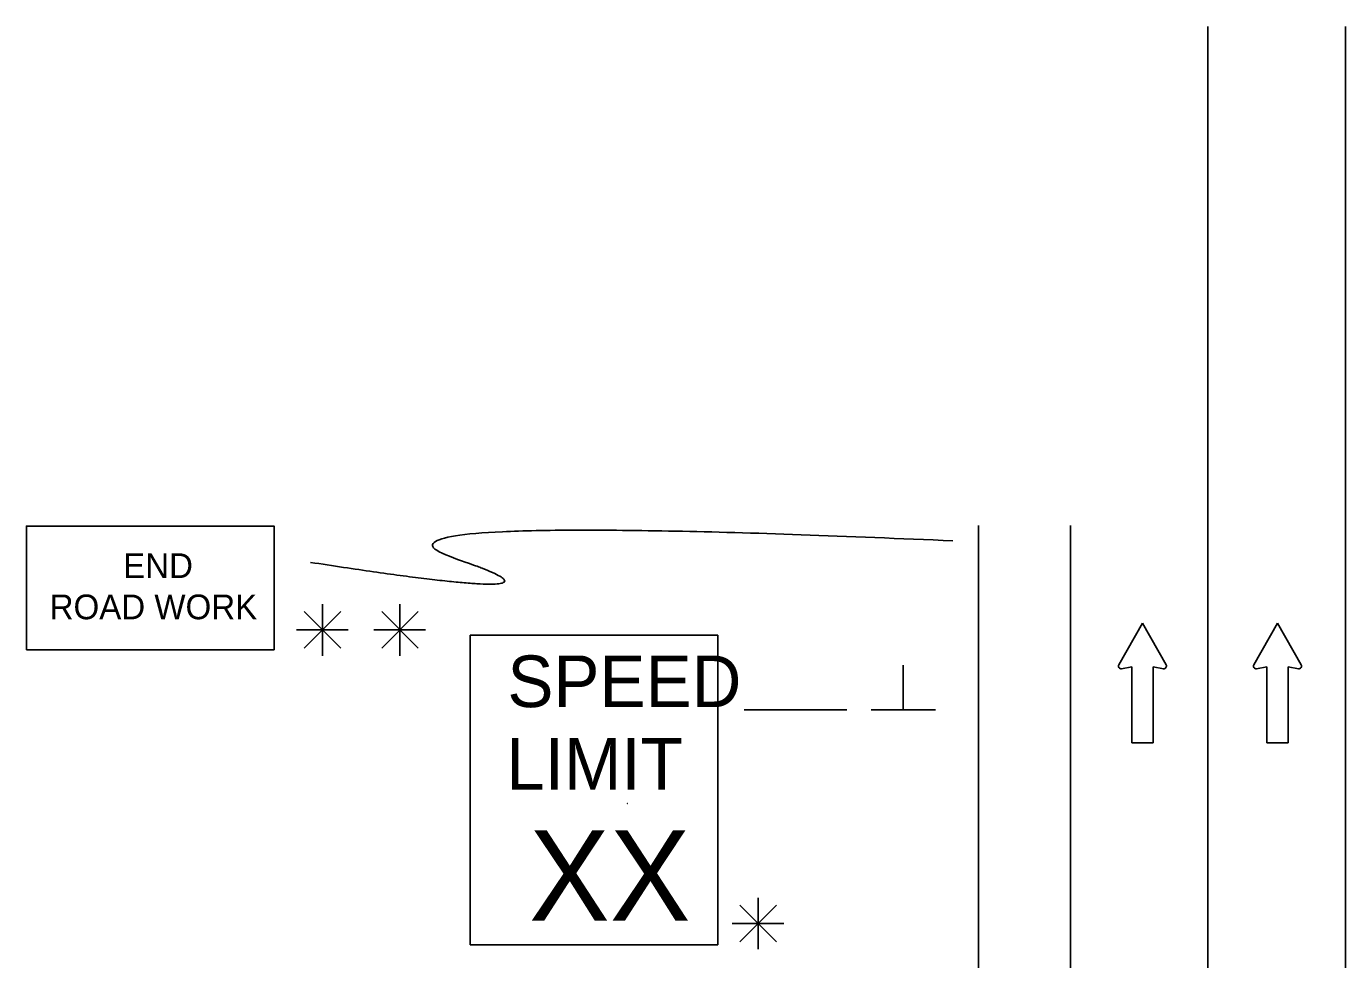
# Model space of a CAD drawing. Extents: x 16726 to 18482, y 5650 to 7013.
# Drawn here: x 16737.3 to 16967.4, y 6850.8 to 7013.5 of the extents above; entities that cross this region are included whole.
import ezdxf

# ---------------------------------------------------------------- set-up
doc = ezdxf.new("R2010")
doc.units = 0
for name, color, linetype in [('ALI_LEGAL_EX', 7, 'Continuous'), ('MT_SCRATCH_LEVEL_E', 7, 'Continuous'), ('PAVT_EDGE_EX', 7, 'Continuous'), ('TRAFFIC_SIGNS_PR', 7, 'Continuous'), ('TYPICAL_TEXT_DIMEN_PR', 7, 'Continuous')]:
    doc.layers.add(name, color=color, linetype=linetype)

msp = doc.modelspace()

# ---------------------------------------------------------------- linework, layer by layer
at = {"layer": 'ALI_LEGAL_EX'}
for p, q in [((16943.36, 7013.47), (16943.36, 6195.33)), ((16967.36, 7013.47), (16967.36, 6195.33)), ((16943.36, 6961.56), (16943.36, 6097.65)), ((16967.36, 6961.56), (16967.36, 6097.65))]:
    msp.add_line(p, q, dxfattribs=at)
for points in [[(16967.36, 6988.47), (16967.36, 7013.47)], [(16943.36, 6924.34), (16943.36, 6899.34)], [(16943.36, 6924.34), (16943.36, 6899.34)], [(16943.36, 6924.34), (16943.36, 6899.34)], [(16943.36, 6924.34), (16943.36, 6899.34)], [(16943.36, 6924.34), (16943.36, 6899.34)], [(16967.36, 6924.34), (16967.36, 6899.34)], [(16967.36, 6924.34), (16967.36, 6899.34)], [(16967.36, 6924.34), (16967.36, 6899.34)], [(16967.36, 6924.34), (16967.36, 6899.34)], [(16967.36, 6924.34), (16967.36, 6899.34)]]:
    msp.add_lwpolyline(points, dxfattribs=at)
at = {"layer": 'MT_SCRATCH_LEVEL_E'}
for p, q in [((16931.92, 6909.41), (16927.81, 6902.17)), ((16936.06, 6902.17), (16931.92, 6909.41)), ((16955.46, 6909.41), (16951.35, 6902.17)), ((16959.61, 6902.17), (16955.46, 6909.41)), ((16928.29, 6901.48), (16930.06, 6901.8)), ((16930.06, 6901.8), (16930.06, 6888.54)), ((16933.81, 6888.54), (16933.81, 6901.8)), ((16933.81, 6901.8), (16935.58, 6901.48)), ((16951.83, 6901.48), (16953.61, 6901.8)), ((16953.61, 6901.8), (16953.61, 6888.54)), ((16957.35, 6888.54), (16957.35, 6901.8)), ((16957.35, 6901.8), (16959.13, 6901.48)), ((16930.06, 6888.54), (16933.81, 6888.54)), ((16953.61, 6888.54), (16957.35, 6888.54))]:
    msp.add_line(p, q, dxfattribs=at)
for centre, start, end in [((16928.21, 6901.94), 150.4248, 279.9638), ((16935.65, 6901.94), 260.0362, 29.7731), ((16951.76, 6901.94), 150.4248, 279.9638), ((16959.2, 6901.94), 260.0362, 29.7731)]:
    msp.add_arc(centre, 0.463, start, end, dxfattribs=at)
at = {"layer": 'PAVT_EDGE_EX'}
for p, q in [((16903.36, 6926.44), (16903.36, 6057.56)), ((16919.36, 6926.44), (16919.36, 6057.56))]:
    msp.add_line(p, q, dxfattribs=at)
at = {"layer": 'TRAFFIC_SIGNS_PR'}
for p, q in [((16814.7, 6907.31), (16857.9, 6907.31)), ((16814.7, 6853.31), (16814.7, 6907.31)), ((16857.9, 6853.31), (16857.9, 6907.31)), ((16814.7, 6853.31), (16857.9, 6853.31))]:
    msp.add_line(p, q, dxfattribs=at)
msp.add_lwpolyline([(16737.31, 6904.77), (16780.51, 6904.77), (16780.51, 6926.36), (16737.31, 6926.36)], close=True, dxfattribs=at)
msp.add_open_spline([(16786.85, 6920.02), (16837.26, 6912.2), (16788.08, 6928.73), (16898.87, 6923.78)], degree=2, dxfattribs=at)
at = {"layer": 'TYPICAL_TEXT_DIMEN_PR'}
for p, q in [((16785.76, 6911.44), (16792.14, 6905.06)), ((16792.14, 6911.44), (16785.76, 6905.06)), ((16788.95, 6908.25), (16788.95, 6912.71)), ((16799.27, 6911.44), (16805.64, 6905.06)), ((16805.64, 6911.44), (16799.27, 6905.06)), ((16802.45, 6908.25), (16802.45, 6912.71)), ((16788.95, 6908.25), (16784.42, 6908.25)), ((16788.95, 6908.25), (16792.14, 6908.25)), ((16788.95, 6908.25), (16793.42, 6908.25)), ((16788.95, 6908.25), (16788.95, 6903.75)), ((16802.45, 6908.25), (16797.92, 6908.25)), ((16802.45, 6908.25), (16805.64, 6908.25)), ((16802.45, 6908.25), (16806.93, 6908.25)), ((16802.45, 6908.25), (16802.45, 6903.75)), ((16890.23, 6894.29), (16890.23, 6902.08)), ((16880.36, 6894.29), (16862.46, 6894.29)), ((16884.61, 6894.29), (16895.86, 6894.29)), ((16861.73, 6860.26), (16868.1, 6853.88)), ((16868.1, 6860.26), (16861.73, 6853.88)), ((16864.92, 6857.07), (16864.92, 6861.53)), ((16864.92, 6857.07), (16860.39, 6857.07)), ((16864.92, 6857.07), (16868.1, 6857.07)), ((16864.92, 6857.07), (16869.4, 6857.07)), ((16864.92, 6857.07), (16864.92, 6852.57))]:
    msp.add_line(p, q, dxfattribs=at)
msp.add_open_spline([(16842.09, 6877.99), (16842.1, 6877.99), (16842.11, 6877.99), (16842.11, 6877.99)], degree=2, dxfattribs=at)

# ---------------------------------------------------------------- texts
at = {"layer": 'TRAFFIC_SIGNS_PR'}
for s, height, p in [('END', 4.31, (16754.18, 6917.29)), ('ROAD WORK', 4.31, (16741.37, 6910.1)), ('SPEED', 9, (16821.19, 6894.78)), ('LIMIT', 9, (16821.01, 6880.38)), ('XX', 15.785, (16824.96, 6857.54))]:
    msp.add_text(s, height=height, dxfattribs=at).set_placement(p)

doc.saveas('drawing.dxf')
